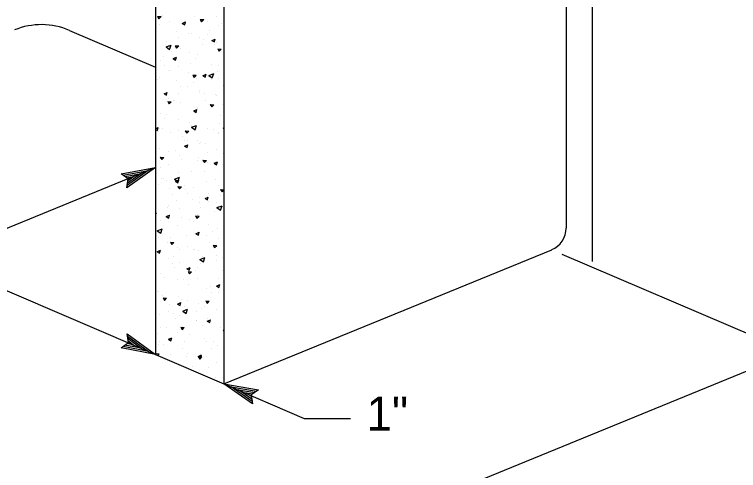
# Model space of a CAD drawing. Extents: x -121933 to -117742, y -103160 to -100084.
# Drawn here: x -120865.6 to -120738.6, y -101489.7 to -101409.8 of the extents above; entities that cross this region are included whole.
import ezdxf

# ---------------------------------------------------------------- set-up
doc = ezdxf.new("R2010")
doc.units = 0
for name, color, linetype in [('G-MARK', 7, 'Continuous'), ('G-TEXT', 7, 'Continuous'), ('Misc CnstDet(22)', 7, 'Continuous')]:
    doc.layers.add(name, color=color, linetype=linetype)

msp = doc.modelspace()

# ---------------------------------------------------------------- linework, layer by layer
at = {"layer": 'G-MARK'}
for p, q in [((-120920.98, -101435.17), (-120840.87, -101469.41)), ((-120720.44, -101472.87), (-120769.57, -101451.87)), ((-120729.29, -101469.09), (-120880.79, -101531.02))]:
    msp.add_line(p, q, dxfattribs=at)
for points in [[(-120840.87, -101436.65), (-120887.68, -101455.78), (-120885.99, -101459.9), (-120894.96, -101453.95), (-120893.28, -101458.07), (-120954.37, -101483.05)], [(-120828.89, -101474.53), (-120814.81, -101480.63), (-120806.7, -101480.63)]]:
    msp.add_lwpolyline(points, dxfattribs=at)
at = {"layer": 'G-TEXT'}
for p, q in [((-120846.92, -101437.72), (-120840.87, -101436.65)), ((-120840.87, -101436.65), (-120845.89, -101440.18)), ((-120840.87, -101436.65), (-120840.87, -101436.65)), ((-120845.67, -101438.65), (-120846.92, -101437.72)), ((-120846.92, -101437.72), (-120846.92, -101437.72)), ((-120846.58, -101437.97), (-120842.14, -101437.18)), ((-120846.23, -101438.21), (-120843.42, -101437.71)), ((-120842.15, -101437.19), (-120845.81, -101439.76)), ((-120843.42, -101437.71), (-120845.78, -101439.37)), ((-120845.93, -101438.46), (-120844.69, -101438.24)), ((-120845.89, -101440.18), (-120845.67, -101438.65)), ((-120844.69, -101438.24), (-120845.71, -101438.95)), ((-120845.89, -101440.18), (-120845.89, -101440.18)), ((-120845.63, -101467.33), (-120845.83, -101465.78)), ((-120845.83, -101465.78), (-120845.83, -101465.78)), ((-120845.83, -101465.78), (-120840.87, -101469.41)), ((-120845.77, -101466.2), (-120842.13, -101468.86)), ((-120845.7, -101466.62), (-120843.4, -101468.3)), ((-120845.68, -101467.01), (-120844.66, -101467.75)), ((-120846.9, -101468.23), (-120845.63, -101467.33)), ((-120840.87, -101469.41), (-120846.9, -101468.23)), ((-120846.9, -101468.23), (-120846.9, -101468.23)), ((-120842.14, -101468.86), (-120846.54, -101468)), ((-120843.4, -101468.3), (-120846.24, -101467.75)), ((-120844.66, -101467.75), (-120845.88, -101467.51)), ((-120840.87, -101469.41), (-120840.87, -101469.41)), ((-120823.85, -101478.05), (-120828.89, -101474.53)), ((-120828.89, -101474.53), (-120828.89, -101474.53)), ((-120828.89, -101474.53), (-120822.83, -101475.58)), ((-120823.91, -101477.64), (-120827.61, -101475.06)), ((-120827.6, -101475.06), (-120823.19, -101475.83)), ((-120823.99, -101477.22), (-120826.33, -101475.58)), ((-120826.33, -101475.58), (-120823.48, -101476.08)), ((-120822.83, -101475.58), (-120824.08, -101476.51)), ((-120822.83, -101475.58), (-120822.83, -101475.58)), ((-120824.02, -101476.83), (-120825.06, -101476.11)), ((-120825.06, -101476.11), (-120823.84, -101476.32)), ((-120824.08, -101476.51), (-120823.85, -101478.05)), ((-120823.85, -101478.05), (-120823.85, -101478.05))]:
    msp.add_line(p, q, dxfattribs=at)
at = {"layer": 'Misc CnstDet(22)'}
for p, q in [((-120764.32, -101368.37), (-120764.32, -101453.12)), ((-120768.88, -101383.08), (-120768.88, -101447.27)), ((-120840.87, -101402.21), (-120840.87, -101469.41)), ((-120828.89, -101407.6), (-120828.89, -101474.53)), ((-120840.54, -101410.16), (-120840.28, -101410.58)), ((-120840.54, -101410.16), (-120839.91, -101410.2)), ((-120840.28, -101410.59), (-120839.91, -101410.2)), ((-120839.61, -101410.02), (-120839.61, -101410.02)), ((-120838.47, -101411.05), (-120838.47, -101411.05)), ((-120836.18, -101411.39), (-120835.62, -101411.13)), ((-120835.75, -101411.64), (-120835.62, -101411.13)), ((-120834.04, -101410.13), (-120834.04, -101410.13)), ((-120833.06, -101410.68), (-120832.8, -101411.11)), ((-120833.06, -101410.68), (-120832.43, -101410.72)), ((-120832.8, -101411.11), (-120832.43, -101410.72)), ((-120831.81, -101411.11), (-120831.81, -101411.11)), ((-120830.12, -101410.11), (-120830.12, -101410.11)), ((-120840.24, -101411.57), (-120840.24, -101411.57)), ((-120836.18, -101411.39), (-120835.75, -101411.64)), ((-120835.64, -101411.35), (-120835.64, -101411.35)), ((-120835.57, -101411.32), (-120835.57, -101411.32)), ((-120829.8, -101411.75), (-120829.8, -101411.75)), ((-120829.29, -101411.43), (-120829.29, -101411.43)), ((-120855.97, -101412.61), (-120840.87, -101419.07)), ((-120837.15, -101412.82), (-120837.15, -101412.82)), ((-120836.83, -101413.79), (-120836.83, -101413.79)), ((-120835.18, -101413.17), (-120835.18, -101413.17)), ((-120834.52, -101413.1), (-120834.52, -101413.1)), ((-120833.17, -101413.8), (-120833.17, -101413.8)), ((-120831.68, -101413.4), (-120831.68, -101413.4)), ((-120831.38, -101412.58), (-120831.38, -101412.58)), ((-120838.93, -101414.49), (-120838.93, -101414.49)), ((-120832.65, -101415.05), (-120832.65, -101415.05)), ((-120832.39, -101414.12), (-120832.39, -101414.12)), ((-120830.99, -101414.39), (-120830.42, -101414.13)), ((-120830.99, -101414.39), (-120830.55, -101414.64)), ((-120830.55, -101414.64), (-120830.42, -101414.13)), ((-120830.14, -101414.76), (-120830.14, -101414.76)), ((-120839.03, -101415.51), (-120838.15, -101415.17)), ((-120839.03, -101415.51), (-120838.4, -101415.93)), ((-120838.56, -101415.22), (-120838.56, -101415.22)), ((-120838.4, -101415.93), (-120838.15, -101415.17)), ((-120838.1, -101416.26), (-120838.1, -101416.26)), ((-120837.45, -101415.3), (-120837.19, -101415.73)), ((-120837.45, -101415.3), (-120836.82, -101415.34)), ((-120837.19, -101415.73), (-120836.82, -101415.34)), ((-120836.55, -101415.85), (-120836.55, -101415.85)), ((-120830.57, -101415.16), (-120830.57, -101415.16)), ((-120829.96, -101415.82), (-120829.71, -101416.25)), ((-120829.96, -101415.82), (-120829.34, -101415.87)), ((-120829.71, -101416.25), (-120829.34, -101415.87)), ((-120839.56, -101417.18), (-120839.56, -101417.18)), ((-120837.78, -101417.56), (-120837.22, -101417.3)), ((-120837.78, -101417.56), (-120837.35, -101417.81)), ((-120837.35, -101417.81), (-120837.22, -101417.3)), ((-120834.98, -101416.54), (-120834.98, -101416.54)), ((-120833.91, -101417.52), (-120833.91, -101417.52)), ((-120833.51, -101416.81), (-120833.51, -101416.81)), ((-120839.93, -101417.9), (-120839.93, -101417.9)), ((-120839.36, -101418.73), (-120839.36, -101418.73)), ((-120836.89, -101418.86), (-120836.89, -101418.86)), ((-120834.8, -101418.48), (-120834.8, -101418.48)), ((-120831.03, -101418.59), (-120831.03, -101418.59)), ((-120829.78, -101418.8), (-120829.78, -101418.8)), ((-120838.52, -101419.69), (-120838.52, -101419.69)), ((-120838.25, -101419.71), (-120838.25, -101419.71)), ((-120835.17, -101420), (-120835.17, -101420)), ((-120830.05, -101419.78), (-120830.05, -101419.78)), ((-120840.62, -101421.2), (-120840.62, -101421.2)), ((-120840.27, -101420.91), (-120840.27, -101420.91)), ((-120834.36, -101420.44), (-120834.1, -101420.87)), ((-120834.36, -101420.44), (-120833.73, -101420.48)), ((-120834.1, -101420.87), (-120833.73, -101420.49)), ((-120833.77, -101420.98), (-120833.77, -101420.98)), ((-120832.59, -101420.56), (-120832.02, -101420.3)), ((-120832.59, -101420.56), (-120832.15, -101420.81)), ((-120832.15, -101420.81), (-120832.02, -101420.3)), ((-120831.83, -101420.46), (-120831.83, -101420.46)), ((-120831.55, -101420.52), (-120830.68, -101420.18)), ((-120831.55, -101420.52), (-120830.93, -101420.94)), ((-120831.05, -101421.27), (-120831.05, -101421.27)), ((-120830.93, -101420.94), (-120830.68, -101420.18)), ((-120829.82, -101421.09), (-120829.82, -101421.09)), ((-120837.13, -101421.47), (-120837.13, -101421.47)), ((-120836.44, -101422.47), (-120836.44, -101422.47)), ((-120835.2, -101422.51), (-120835.2, -101422.51)), ((-120834.3, -101421.76), (-120834.3, -101421.76)), ((-120829.01, -101422.28), (-120829.01, -101422.28)), ((-120839.38, -101423.73), (-120838.82, -101423.47)), ((-120839.38, -101423.73), (-120838.95, -101423.98)), ((-120838.95, -101423.98), (-120838.82, -101423.47)), ((-120836.87, -101423.67), (-120836.87, -101423.67)), ((-120833.2, -101423.14), (-120833.2, -101423.14)), ((-120833.18, -101423.52), (-120833.18, -101423.52)), ((-120832.31, -101423.74), (-120832.31, -101423.74)), ((-120830.34, -101423.81), (-120830.34, -101423.81)), ((-120838.75, -101425.06), (-120838.49, -101425.49)), ((-120838.75, -101425.06), (-120838.12, -101425.1)), ((-120838.58, -101424.56), (-120838.58, -101424.56)), ((-120838.49, -101425.49), (-120838.12, -101425.11)), ((-120837.7, -101424.94), (-120837.7, -101424.94)), ((-120837.59, -101424.9), (-120837.59, -101424.9)), ((-120836.57, -101425.19), (-120836.57, -101425.19)), ((-120832.12, -101424.97), (-120832.12, -101424.97)), ((-120830.16, -101424.1), (-120830.16, -101424.1)), ((-120834.19, -101426.73), (-120833.62, -101426.47)), ((-120833.76, -101426.98), (-120833.62, -101426.47)), ((-120833.58, -101426.21), (-120833.58, -101426.21)), ((-120833.54, -101426.15), (-120833.54, -101426.15)), ((-120831.27, -101425.58), (-120831.01, -101426.01)), ((-120831.27, -101425.58), (-120830.64, -101425.63)), ((-120831.01, -101426.02), (-120830.64, -101425.63)), ((-120829.22, -101425.57), (-120829.22, -101425.57)), ((-120839.95, -101427.25), (-120839.95, -101427.25)), ((-120838.97, -101427.41), (-120838.97, -101427.41)), ((-120834.19, -101426.73), (-120833.76, -101426.98)), ((-120833.64, -101426.95), (-120833.64, -101426.95)), ((-120829.54, -101427.51), (-120829.54, -101427.51)), ((-120840.86, -101428.07), (-120840.86, -101428.07)), ((-120839.29, -101428.04), (-120839.29, -101428.04)), ((-120836.91, -101428.2), (-120836.91, -101428.2)), ((-120834.84, -101428.69), (-120834.84, -101428.69)), ((-120829.68, -101429), (-120829.68, -101429)), ((-120840.87, -101429.84), (-120840.42, -101429.64)), ((-120840.87, -101429.97), (-120840.55, -101430.15)), ((-120840.55, -101430.15), (-120840.42, -101429.64)), ((-120840.29, -101430.26), (-120840.29, -101430.26)), ((-120840.23, -101429.88), (-120840.23, -101429.88)), ((-120839.74, -101429.83), (-120839.74, -101429.83)), ((-120836.91, -101430.12), (-120836.91, -101430.12)), ((-120835.66, -101430.2), (-120835.4, -101430.63)), ((-120835.66, -101430.2), (-120835.03, -101430.25)), ((-120835.4, -101430.64), (-120835.03, -101430.25)), ((-120834.56, -101429.59), (-120833.69, -101429.25)), ((-120834.56, -101429.59), (-120833.94, -101430.01)), ((-120834.53, -101429.33), (-120834.53, -101429.33)), ((-120833.94, -101430.01), (-120833.69, -101429.26)), ((-120831.85, -101429.8), (-120831.85, -101429.8)), ((-120830.8, -101429.98), (-120830.8, -101429.98)), ((-120828.99, -101429.73), (-120828.89, -101429.68)), ((-120828.99, -101429.73), (-120828.89, -101429.79)), ((-120838.25, -101430.54), (-120838.25, -101430.54)), ((-120836.11, -101431.16), (-120836.11, -101431.16)), ((-120829.84, -101430.43), (-120829.84, -101430.43)), ((-120829.77, -101430.63), (-120829.77, -101430.63)), ((-120835.79, -101431.88), (-120835.79, -101431.88)), ((-120835.79, -101432.9), (-120835.22, -101432.64)), ((-120835.36, -101433.15), (-120835.22, -101432.64)), ((-120835.23, -101431.85), (-120835.23, -101431.85)), ((-120833.49, -101431.84), (-120833.49, -101431.84)), ((-120833.22, -101432.48), (-120833.22, -101432.48)), ((-120832.95, -101432.17), (-120832.95, -101432.17)), ((-120832.06, -101432.45), (-120832.06, -101432.45)), ((-120840.2, -101433.26), (-120840.2, -101433.26)), ((-120838.6, -101433.9), (-120838.6, -101433.9)), ((-120837.37, -101433.63), (-120837.37, -101433.63)), ((-120835.79, -101432.9), (-120835.36, -101433.15)), ((-120831.83, -101433.93), (-120831.83, -101433.93)), ((-120830.18, -101433.44), (-120830.18, -101433.44)), ((-120840.05, -101434.82), (-120839.79, -101435.25)), ((-120840.05, -101434.82), (-120839.43, -101434.87)), ((-120839.79, -101435.25), (-120839.43, -101434.87)), ((-120836.6, -101434.53), (-120836.6, -101434.53)), ((-120836.59, -101434.54), (-120836.59, -101434.54)), ((-120836.25, -101435.31), (-120836.25, -101435.31)), ((-120833.33, -101434.92), (-120833.33, -101434.92)), ((-120832.57, -101435.35), (-120832.31, -101435.78)), ((-120832.57, -101435.35), (-120831.94, -101435.39)), ((-120829, -101434.22), (-120829, -101434.22)), ((-120839.97, -101436.59), (-120839.97, -101436.59)), ((-120838.63, -101436.1), (-120838.63, -101436.1)), ((-120833.56, -101435.49), (-120833.56, -101435.49)), ((-120832.31, -101435.78), (-120831.94, -101435.39)), ((-120831.84, -101435.82), (-120831.84, -101435.82)), ((-120830.59, -101435.9), (-120830.03, -101435.64)), ((-120830.59, -101435.9), (-120830.16, -101436.15)), ((-120830.16, -101436.15), (-120830.03, -101435.64)), ((-120829.14, -101436.19), (-120829.14, -101436.19)), ((-120836.93, -101437.55), (-120836.93, -101437.55)), ((-120834.59, -101437.4), (-120834.59, -101437.4)), ((-120832.29, -101437.36), (-120832.29, -101437.36)), ((-120839.9, -101438.57), (-120839.9, -101438.57)), ((-120839.52, -101438.48), (-120839.52, -101438.48)), ((-120839.01, -101438.89), (-120839.01, -101438.89)), ((-120837.57, -101438.67), (-120836.7, -101438.33)), ((-120837.57, -101438.67), (-120836.95, -101439.08)), ((-120837.39, -101439.07), (-120836.82, -101438.81)), ((-120837.39, -101439.07), (-120836.96, -101439.32)), ((-120836.96, -101439.32), (-120836.82, -101438.81)), ((-120836.95, -101439.09), (-120836.7, -101438.33)), ((-120831.87, -101439.14), (-120831.87, -101439.14)), ((-120830.41, -101438.66), (-120830.41, -101438.66)), ((-120840.31, -101439.6), (-120840.31, -101439.6)), ((-120838.4, -101440.24), (-120838.4, -101440.24)), ((-120836.96, -101439.97), (-120836.7, -101440.4)), ((-120836.96, -101439.97), (-120836.34, -101440.01)), ((-120836.7, -101440.4), (-120836.34, -101440.01)), ((-120835.86, -101439.87), (-120835.86, -101439.87)), ((-120834.25, -101440.18), (-120834.25, -101440.18)), ((-120829.87, -101439.78), (-120829.87, -101439.78)), ((-120837.97, -101441.39), (-120837.97, -101441.39)), ((-120835.57, -101440.54), (-120835.57, -101440.54)), ((-120835.25, -101441.19), (-120835.25, -101441.19)), ((-120831.67, -101441.13), (-120831.67, -101441.13)), ((-120829.5, -101441.48), (-120829.5, -101441.48)), ((-120829.48, -101440.49), (-120829.22, -101440.92)), ((-120829.48, -101440.49), (-120828.89, -101440.53)), ((-120829.22, -101440.92), (-120828.89, -101440.57)), ((-120837.12, -101442.34), (-120837.12, -101442.34)), ((-120834.45, -101442.29), (-120834.45, -101442.29)), ((-120833.24, -101441.83), (-120833.24, -101441.83)), ((-120833.22, -101442.69), (-120833.22, -101442.69)), ((-120832.19, -101442.07), (-120831.63, -101441.81)), ((-120832.19, -101442.07), (-120831.76, -101442.32)), ((-120831.76, -101442.32), (-120831.63, -101441.81)), ((-120831.61, -101442.59), (-120831.61, -101442.59)), ((-120830.21, -101442.78), (-120830.21, -101442.78)), ((-120838.86, -101443.67), (-120838.86, -101443.67)), ((-120838.62, -101443.25), (-120838.62, -101443.25)), ((-120836.62, -101443.88), (-120836.62, -101443.88)), ((-120832.94, -101443.6), (-120832.94, -101443.6)), ((-120830.1, -101443.67), (-120829.22, -101443.34)), ((-120830.1, -101443.67), (-120829.47, -101444.09)), ((-120829.47, -101444.09), (-120829.22, -101443.34)), ((-120840.87, -101444.62), (-120840.73, -101444.63)), ((-120840.87, -101444.78), (-120840.73, -101444.63)), ((-120838.99, -101445.24), (-120838.43, -101444.98)), ((-120838.99, -101445.24), (-120838.56, -101445.49)), ((-120838.56, -101445.49), (-120838.43, -101444.98)), ((-120838.39, -101444.81), (-120838.39, -101444.81)), ((-120836.32, -101445.38), (-120836.32, -101445.38)), ((-120833.87, -101445.11), (-120833.61, -101445.54)), ((-120833.87, -101445.11), (-120833.25, -101445.15)), ((-120833.61, -101445.54), (-120833.24, -101445.16)), ((-120833.58, -101444.84), (-120833.58, -101444.84)), ((-120830.49, -101444.34), (-120830.49, -101444.34)), ((-120839.99, -101445.93), (-120839.99, -101445.93)), ((-120834.91, -101445.72), (-120834.91, -101445.72)), ((-120834.2, -101446.07), (-120834.2, -101446.07)), ((-120831.57, -101446.68), (-120831.57, -101446.68)), ((-120840.59, -101447.74), (-120839.71, -101447.4)), ((-120840.59, -101447.74), (-120839.96, -101448.16)), ((-120839.96, -101448.16), (-120839.71, -101447.4)), ((-120839.65, -101447.28), (-120839.65, -101447.28)), ((-120836.96, -101446.89), (-120836.96, -101446.89)), ((-120833.8, -101448.24), (-120833.23, -101447.98)), ((-120833.36, -101448.49), (-120833.23, -101447.98)), ((-120830.95, -101447.77), (-120830.95, -101447.77)), ((-120830.07, -101447.35), (-120830.07, -101447.35)), ((-120840.33, -101448.94), (-120840.33, -101448.94)), ((-120838.18, -101448.9), (-120838.18, -101448.9)), ((-120835.46, -101448.54), (-120835.46, -101448.54)), ((-120833.8, -101448.24), (-120833.36, -101448.49)), ((-120831.89, -101448.49), (-120831.89, -101448.49)), ((-120829.89, -101449.12), (-120829.89, -101449.12)), ((-120838.74, -101449.74), (-120838.74, -101449.74)), ((-120838.26, -101449.73), (-120838, -101450.16)), ((-120838.26, -101449.73), (-120837.64, -101449.77)), ((-120838, -101450.16), (-120837.64, -101449.78)), ((-120835.27, -101450.54), (-120835.27, -101450.54)), ((-120831.34, -101449.82), (-120831.34, -101449.82)), ((-120830.78, -101450.25), (-120830.52, -101450.68)), ((-120830.78, -101450.25), (-120830.16, -101450.3)), ((-120830.52, -101450.68), (-120830.15, -101450.3)), ((-120840.59, -101451.41), (-120840.03, -101451.15)), ((-120840.59, -101451.41), (-120840.16, -101451.66)), ((-120840.16, -101451.66), (-120840.03, -101451.15)), ((-120837.06, -101450.65), (-120837.06, -101450.65)), ((-120836.73, -101451.02), (-120836.73, -101451.02)), ((-120834.22, -101450.95), (-120834.22, -101450.95)), ((-120833.98, -101451.04), (-120833.98, -101451.04)), ((-120833.26, -101451.17), (-120833.26, -101451.17)), ((-120828.89, -101474.53), (-120771.41, -101451.04)), ((-120838.65, -101452.59), (-120838.65, -101452.59)), ((-120837.7, -101452.24), (-120837.7, -101452.24)), ((-120833.11, -101452.75), (-120832.24, -101452.41)), ((-120833.11, -101452.75), (-120832.49, -101453.17)), ((-120833.1, -101452.7), (-120833.1, -101452.7)), ((-120832.6, -101452.29), (-120832.6, -101452.29)), ((-120832.49, -101453.17), (-120832.23, -101452.41)), ((-120830.27, -101453), (-120830.27, -101453)), ((-120830.23, -101452.13), (-120830.23, -101452.13)), ((-120829.22, -101452.33), (-120829.22, -101452.33)), ((-120837.99, -101453.49), (-120837.99, -101453.49)), ((-120837.52, -101454.09), (-120837.52, -101454.09)), ((-120836.64, -101453.22), (-120836.64, -101453.22)), ((-120835.4, -101454.41), (-120834.83, -101454.15)), ((-120835.4, -101454.41), (-120834.96, -101454.66)), ((-120834.96, -101454.66), (-120834.83, -101454.15)), ((-120833.6, -101454.18), (-120833.6, -101454.18)), ((-120832.94, -101453.54), (-120832.94, -101453.54)), ((-120840.8, -101454.93), (-120840.8, -101454.93)), ((-120840.02, -101455.28), (-120840.02, -101455.28)), ((-120835.17, -101454.87), (-120834.91, -101455.3)), ((-120835.17, -101454.87), (-120834.55, -101454.92)), ((-120834.91, -101455.3), (-120834.55, -101454.92)), ((-120833.87, -101454.76), (-120833.87, -101454.76)), ((-120829.15, -101454.76), (-120829.15, -101454.76)), ((-120839.26, -101455.96), (-120839.26, -101455.96)), ((-120836.98, -101456.23), (-120836.98, -101456.23)), ((-120836.05, -101456.23), (-120836.05, -101456.23)), ((-120833.56, -101456.14), (-120833.56, -101456.14)), ((-120829.83, -101456.06), (-120829.83, -101456.06)), ((-120840.79, -101457.26), (-120840.79, -101457.26)), ((-120835.13, -101457.23), (-120835.13, -101457.23)), ((-120831.92, -101457.83), (-120831.92, -101457.83)), ((-120831.29, -101457.53), (-120831.29, -101457.53)), ((-120830.2, -101457.41), (-120829.63, -101457.15)), ((-120830.2, -101457.41), (-120829.77, -101457.66)), ((-120829.77, -101457.66), (-120829.63, -101457.15)), ((-120829.61, -101458.19), (-120829.61, -101458.19)), ((-120840.52, -101458.43), (-120840.52, -101458.43)), ((-120840.35, -101458.29), (-120840.35, -101458.29)), ((-120839.67, -101459.02), (-120839.67, -101459.02)), ((-120839.56, -101459.49), (-120839.3, -101459.92)), ((-120839.56, -101459.49), (-120838.94, -101459.54)), ((-120836.83, -101459.31), (-120836.83, -101459.31)), ((-120831.09, -101458.53), (-120831.09, -101458.53)), ((-120829.91, -101458.46), (-120829.91, -101458.46)), ((-120839.3, -101459.92), (-120838.94, -101459.54)), ((-120838.46, -101460.59), (-120838.46, -101460.59)), ((-120837, -101460.58), (-120836.43, -101460.31)), ((-120837, -101460.58), (-120836.57, -101460.83)), ((-120836.56, -101460.83), (-120836.43, -101460.32)), ((-120836.39, -101459.71), (-120836.39, -101459.71)), ((-120835.29, -101459.88), (-120835.29, -101459.88)), ((-120833.29, -101460.51), (-120833.29, -101460.51)), ((-120832.08, -101460.02), (-120831.82, -101460.44)), ((-120832.08, -101460.02), (-120831.46, -101460.06)), ((-120831.82, -101460.45), (-120831.46, -101460.06)), ((-120838.67, -101461.93), (-120838.67, -101461.93)), ((-120836.12, -101461.82), (-120835.25, -101461.48)), ((-120836.12, -101461.82), (-120835.5, -101462.24)), ((-120835.72, -101461.07), (-120835.72, -101461.07)), ((-120835.5, -101462.24), (-120835.25, -101461.49)), ((-120833.7, -101461.89), (-120833.7, -101461.89)), ((-120832.88, -101461.36), (-120832.88, -101461.36)), ((-120832.35, -101461), (-120832.35, -101461)), ((-120830.25, -101461.47), (-120830.25, -101461.47)), ((-120840.13, -101462.45), (-120840.13, -101462.45)), ((-120837.66, -101462.18), (-120837.66, -101462.18)), ((-120837.42, -101463.09), (-120837.42, -101463.09)), ((-120836.66, -101462.57), (-120836.66, -101462.57)), ((-120831.8, -101463.58), (-120831.24, -101463.31)), ((-120831.76, -101463.12), (-120831.76, -101463.12)), ((-120831.37, -101463.83), (-120831.24, -101463.32)), ((-120828.95, -101463.19), (-120828.95, -101463.19)), ((-120836.18, -101464.5), (-120836.18, -101464.5)), ((-120833.63, -101463.52), (-120833.63, -101463.52)), ((-120833.62, -101463.47), (-120833.62, -101463.47)), ((-120832.67, -101464.39), (-120832.67, -101464.39)), ((-120831.8, -101463.58), (-120831.37, -101463.83)), ((-120828.93, -101463.41), (-120828.93, -101463.41)), ((-120840.53, -101465.78), (-120840.53, -101465.78)), ((-120840.04, -101464.62), (-120840.04, -101464.62)), ((-120838.92, -101464.65), (-120838.92, -101464.65)), ((-120837, -101465.58), (-120837, -101465.58)), ((-120836.47, -101464.64), (-120836.21, -101465.06)), ((-120836.47, -101464.64), (-120835.85, -101464.68)), ((-120836.21, -101465.07), (-120835.85, -101464.68)), ((-120829.43, -101464.74), (-120829.43, -101464.74)), ((-120828.99, -101465.16), (-120828.89, -101465.33)), ((-120828.99, -101465.16), (-120828.89, -101465.17)), ((-120840.19, -101467.12), (-120840.19, -101467.12)), ((-120838.6, -101466.75), (-120838.03, -101466.48)), ((-120838.6, -101466.75), (-120838.17, -101467)), ((-120838.17, -101467), (-120838.03, -101466.49)), ((-120835.77, -101467.08), (-120835.77, -101467.08)), ((-120834.88, -101465.94), (-120834.88, -101465.94)), ((-120832.22, -101466.55), (-120832.22, -101466.55)), ((-120840.38, -101467.63), (-120840.38, -101467.63)), ((-120839.45, -101467.67), (-120839.45, -101467.67)), ((-120831.94, -101467.17), (-120831.94, -101467.17)), ((-120831.02, -101468.38), (-120831.02, -101468.38)), ((-120830.7, -101467.21), (-120830.7, -101467.21)), ((-120829.93, -101467.8), (-120829.93, -101467.8)), ((-120840.87, -101469.41), (-120828.89, -101474.53)), ((-120840.86, -101469.26), (-120840.74, -101469.47)), ((-120840.86, -101469.26), (-120840.24, -101469.3)), ((-120840.49, -101469.57), (-120840.24, -101469.3)), ((-120838.33, -101469.43), (-120838.33, -101469.43)), ((-120836.15, -101468.42), (-120836.15, -101468.42)), ((-120835.31, -101469.22), (-120835.31, -101469.22)), ((-120833.4, -101469.75), (-120832.84, -101469.48)), ((-120832.97, -101470), (-120832.84, -101469.49)), ((-120837.41, -101470.89), (-120837.41, -101470.89)), ((-120835.49, -101469.72), (-120835.49, -101469.72)), ((-120833.4, -101469.75), (-120832.97, -101470)), ((-120833.38, -101469.78), (-120833.12, -101470.21)), ((-120833.38, -101469.78), (-120832.76, -101469.82)), ((-120833.31, -101469.86), (-120833.31, -101469.86)), ((-120833.12, -101470.21), (-120832.76, -101469.82)), ((-120831.96, -101469.68), (-120831.96, -101469.68)), ((-120830.27, -101470.81), (-120830.27, -101470.81)), ((-120834.37, -101471.48), (-120834.37, -101471.48)), ((-120833.22, -101472.15), (-120833.22, -101472.15)), ((-120831.54, -101471.77), (-120831.54, -101471.77)), ((-120829.1, -101473.43), (-120829.1, -101473.43)), ((-120830.42, -101473.53), (-120830.42, -101473.53))]:
    msp.add_line(p, q, dxfattribs=at)
for centre, radius, start, end in [((-120860.88, -101424.1), 12.5, 66.8572, 112.2327), ((-120772.95, -101447.27), 4.07, 292.2327, 0)]:
    msp.add_arc(centre, radius, start, end, dxfattribs=at)

# ---------------------------------------------------------------- texts
msp.add_text('1"', height=6, dxfattribs=at).set_placement((-120803.89, -101482.78))

doc.saveas('drawing.dxf')
